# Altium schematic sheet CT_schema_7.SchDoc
size 274 x 160 mm
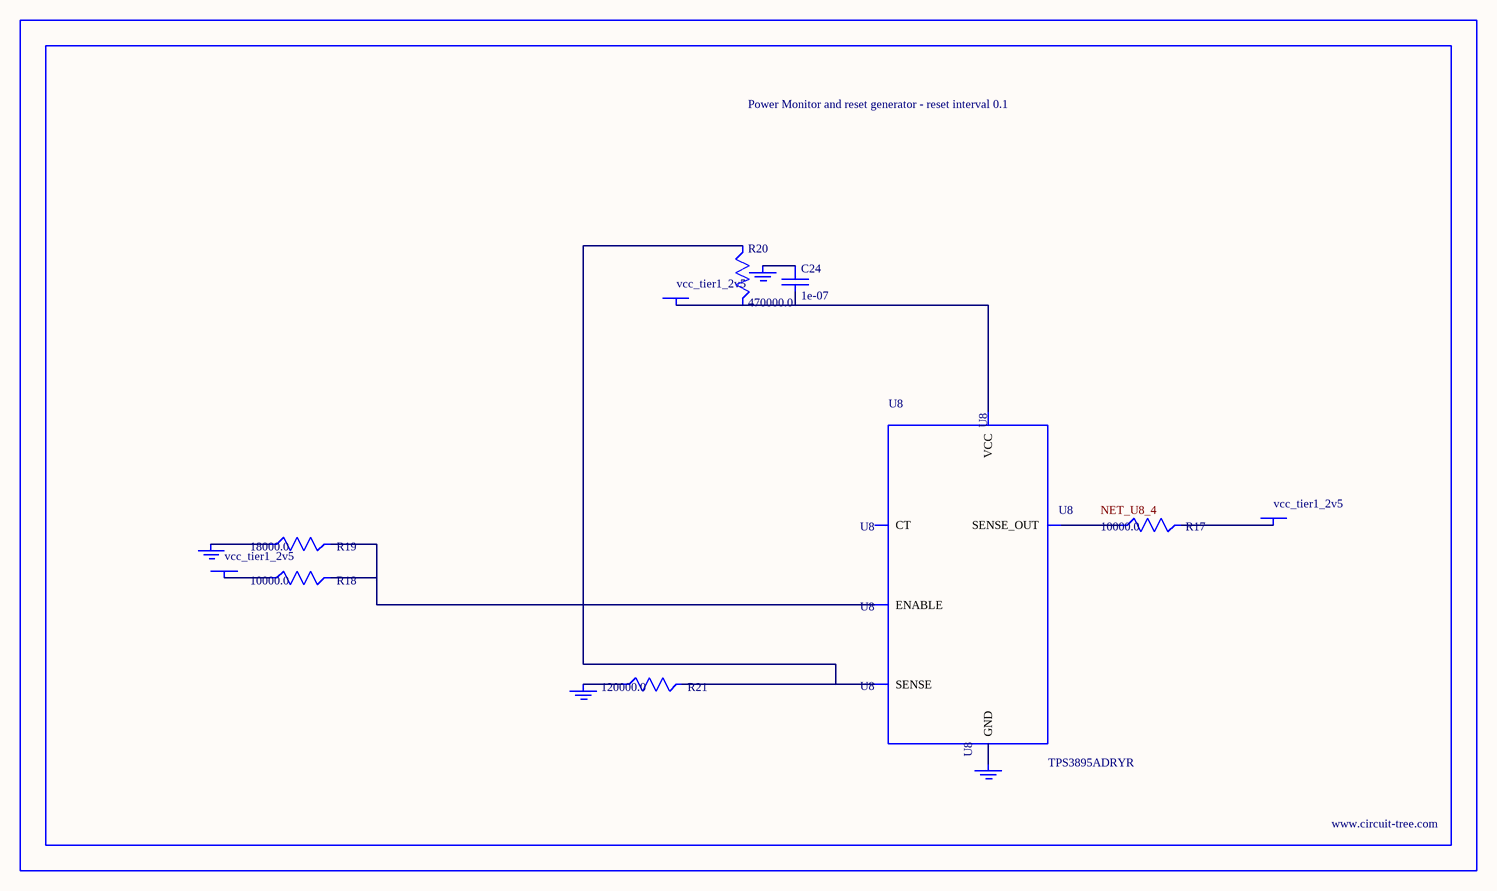
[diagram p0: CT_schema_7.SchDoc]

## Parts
BORDER6  (no value)
C24  1e-07  [C0402]
GND_INSTANCE_6_0  (no value)
GND_INSTANCE_6_1  (no value)
GND_INSTANCE_6_2  (no value)
GND_INSTANCE_6_3  (no value)
POWER_INSTANCE_6_0  vcc_tier1_2v5
POWER_INSTANCE_6_1  vcc_tier1_2v5
POWER_INSTANCE_6_2  vcc_tier1_2v5
R17  10000.0  [R0603]
R18  10000.0  [R0603]
R19  18000.0  [R0603]
R20  470000.0  [R0603]
R21  120000.0  [R0603]
U8  TPS3895ADRYR  [SON-6]

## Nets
NetC24_1: C24.1 GND_INSTANCE_6_2.0(GND)
NetC24_2: C24.2 POWER_INSTANCE_6_2.0(PWR) R20.2 U8.6(VCC)
NetGND_INSTANCE_6_0_0: GND_INSTANCE_6_0.0(GND) R19.1
NetGND_INSTANCE_6_1_0: GND_INSTANCE_6_1.0(GND) R21.1
NetGND_INSTANCE_6_3_0: GND_INSTANCE_6_3.0(GND) U8.2(GND)
NetPOWER_INSTANCE_6_0_0: POWER_INSTANCE_6_0.0(PWR) R18.1
NetPOWER_INSTANCE_6_1_0: POWER_INSTANCE_6_1.0(PWR) R17.2
NetR17_1: R17.1 U8.4(SENSE_OUT)
NetR18_2: R18.2 R19.2 U8.1(ENABLE)
NetR20_1: R20.1 R21.2 U8.3(SENSE)

Not connected (* = marked no-connect by the designer): U8 5(CT)

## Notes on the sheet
- Labels drawn without touching a wire or pin: NET_U8_4

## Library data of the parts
BORDER6 = BORDER_PAGE6
C24 = C0402C104K3RACTU
GND_INSTANCE_6_0-GND_INSTANCE_6_3 = GND
POWER_INSTANCE_6_0-POWER_INSTANCE_6_2 = PWR
R17 R18 = RC0603JR-0710KL
R19 = RC0603JR-0718KL
R20 = RC0603JR-07470KL
R21 = RC0603JR-07120KL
